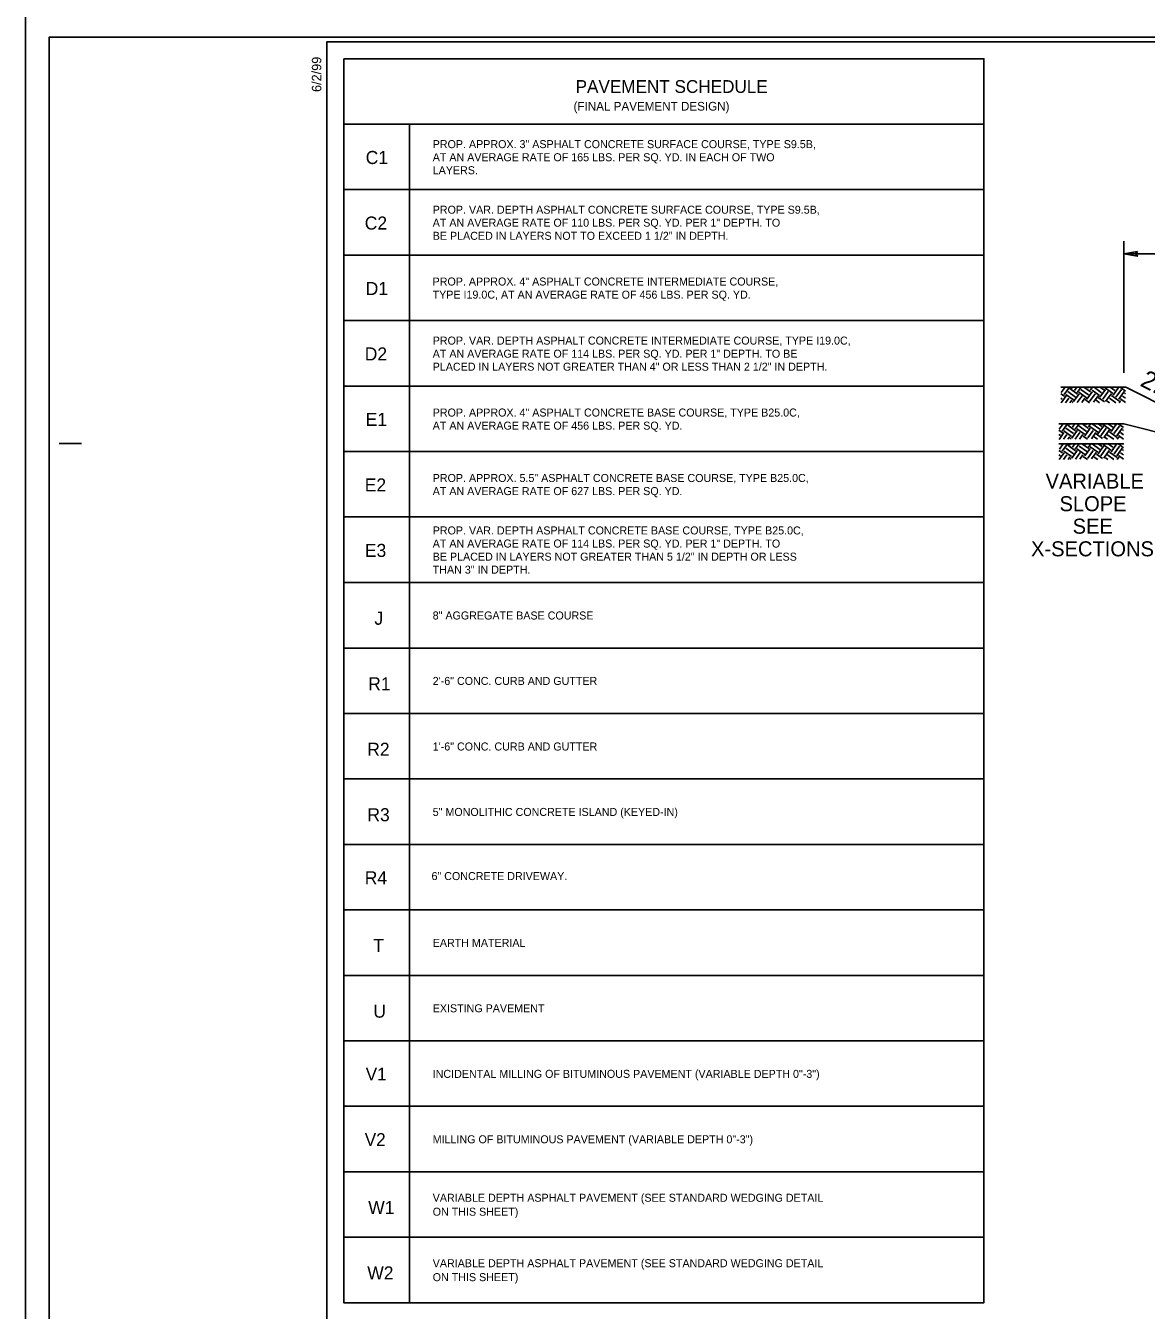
# Model space of a CAD drawing. Extents: x 3025871 to 3026431, y 707165 to 707825.
# Drawn here: x 3026022 to 3026115.2, y 707626.1 to 707732.9 of the extents above; entities that cross this region are included whole.
import ezdxf

# ---------------------------------------------------------------- set-up
doc = ezdxf.new("R2010")
doc.units = 0
for name, color, linetype in [('Default', 7, 'Continuous'), ('Old_Level_39', 7, 'Continuous'), ('Prop Drainage Structure Plot Symbol 20 Scale', 7, 'Continuous'), ('Sheet Cutting Line CELL', 7, 'Continuous'), ('Typical Guardrail CELL', 7, 'Continuous'), ('Typical ID Circle CELL', 7, 'Continuous'), ('Typical Shoulder Slope CELL', 7, 'Continuous'), ('Typical Terminator CELL', 7, 'Continuous'), ('Typical Text Centerline CELL', 7, 'Continuous'), ('Typical Text Grade Point CELL', 7, 'Continuous')]:
    doc.layers.add(name, color=color, linetype=linetype)

msp = doc.modelspace()

# ---------------------------------------------------------------- linework, layer by layer
at = {"layer": 'Default'}
msp.add_line((3026048.47, 707627.53), (3026048.47, 707627.53), dxfattribs=at)
msp.add_lwpolyline([(3026048.47, 707730.18), (3026101.69, 707730.18), (3026101.69, 707724.74), (3026048.47, 707724.74)], close=True, dxfattribs=at)
at = {"layer": 'Old_Level_39'}
msp.add_lwpolyline([(3026273.95, 707731.97), (3026023.97, 707731.97), (3026023.97, 707573.7), (3026273.95, 707573.7)], close=True, dxfattribs=at)
at = {"layer": 'Sheet Cutting Line CELL'}
msp.add_line((3026024.8, 707698.21), (3026026.67, 707698.21), dxfattribs=at)
msp.add_lwpolyline([(3026272.07, 707731.59), (3026047.07, 707731.59), (3026047.07, 707574.09), (3026272.07, 707574.09)], close=True, dxfattribs=at)
at = {"layer": 'Typical Guardrail CELL'}
for p, q in [((3026111.65, 707702.72), (3026111.66, 707702.7)), ((3026113.47, 707702.88), (3026125.81, 707696.71)), ((3026111.66, 707699.7), (3026111.67, 707699.68)), ((3026113.31, 707699.84), (3026125.81, 707696.71)), ((3026111.66, 707698.03), (3026111.67, 707698.01))]:
    msp.add_line(p, q, dxfattribs=at)
at = {"layer": 'Typical ID Circle CELL'}
for points in [[(3026053.92, 707719.3), (3026048.47, 707719.3), (3026048.47, 707724.74), (3026101.69, 707724.74), (3026101.69, 707719.3), (3026053.92, 707719.3), (3026053.92, 707724.74)], [(3026053.92, 707713.86), (3026048.47, 707713.86), (3026048.47, 707719.3), (3026101.69, 707719.3), (3026101.69, 707713.86), (3026053.92, 707713.86), (3026053.92, 707719.3)], [(3026053.92, 707708.41), (3026048.47, 707708.41), (3026048.47, 707713.86), (3026101.69, 707713.86), (3026101.69, 707708.41), (3026053.92, 707708.41), (3026053.92, 707713.86)], [(3026053.92, 707702.97), (3026048.47, 707702.97), (3026048.47, 707708.41), (3026101.69, 707708.41), (3026101.69, 707702.97), (3026053.92, 707702.97), (3026053.92, 707708.41)], [(3026053.92, 707697.53), (3026048.47, 707697.53), (3026048.47, 707702.97), (3026101.69, 707702.97), (3026101.69, 707697.53), (3026053.92, 707697.53), (3026053.92, 707702.97)], [(3026053.92, 707692.09), (3026048.47, 707692.09), (3026048.47, 707697.53), (3026101.69, 707697.53), (3026101.69, 707692.09), (3026053.92, 707692.09), (3026053.92, 707697.53)], [(3026053.92, 707686.65), (3026048.47, 707686.65), (3026048.47, 707692.09), (3026101.69, 707692.09), (3026101.69, 707686.65), (3026053.92, 707686.65), (3026053.92, 707692.09)], [(3026053.92, 707681.2), (3026048.47, 707681.2), (3026048.47, 707686.65), (3026101.69, 707686.65), (3026101.69, 707681.2), (3026053.92, 707681.2), (3026053.92, 707686.65)], [(3026053.92, 707675.76), (3026048.47, 707675.76), (3026048.47, 707681.2), (3026101.69, 707681.2), (3026101.69, 707675.76), (3026053.92, 707675.76), (3026053.92, 707681.2)], [(3026053.92, 707670.32), (3026048.47, 707670.32), (3026048.47, 707675.76), (3026101.69, 707675.76), (3026101.69, 707670.32), (3026053.92, 707670.32), (3026053.92, 707675.76)], [(3026053.92, 707664.88), (3026048.47, 707664.88), (3026048.47, 707670.32), (3026101.69, 707670.32), (3026101.69, 707664.88), (3026053.92, 707664.88), (3026053.92, 707670.32)], [(3026053.92, 707659.43), (3026048.47, 707659.43), (3026048.47, 707664.88), (3026101.69, 707664.88), (3026101.69, 707659.43), (3026053.92, 707659.43), (3026053.92, 707664.88)], [(3026053.92, 707653.99), (3026048.47, 707653.99), (3026048.47, 707659.44), (3026101.69, 707659.44), (3026101.69, 707653.99), (3026053.92, 707653.99), (3026053.92, 707659.44)], [(3026053.92, 707648.55), (3026048.47, 707648.55), (3026048.47, 707653.99), (3026101.69, 707653.99), (3026101.69, 707648.55), (3026053.92, 707648.55), (3026053.92, 707653.99)], [(3026053.92, 707643.11), (3026048.47, 707643.11), (3026048.47, 707648.55), (3026101.69, 707648.55), (3026101.69, 707643.11), (3026053.92, 707643.11), (3026053.92, 707648.55)], [(3026053.92, 707637.67), (3026048.47, 707637.67), (3026048.47, 707643.11), (3026101.69, 707643.11), (3026101.69, 707637.67), (3026053.92, 707637.67), (3026053.92, 707643.11)], [(3026053.92, 707632.22), (3026048.47, 707632.22), (3026048.47, 707637.67), (3026101.69, 707637.67), (3026101.69, 707632.22), (3026053.92, 707632.22), (3026053.92, 707637.67)], [(3026053.92, 707626.78), (3026048.47, 707626.78), (3026048.47, 707632.22), (3026101.69, 707632.22), (3026101.69, 707626.78), (3026053.92, 707626.78), (3026053.92, 707632.22)]]:
    msp.add_lwpolyline(points, dxfattribs=at)
at = {"layer": 'Typical Shoulder Slope CELL'}
for p, q in [((3026113.31, 707704.08), (3026113.31, 707715.03)), ((3026125.81, 707713.96), (3026113.31, 707713.96))]:
    msp.add_line(p, q, dxfattribs=at)
at = {"layer": 'Typical Terminator CELL'}
msp.add_lwpolyline([(3026274.62, 707735.34), (3026022.02, 707735.34), (3026022.02, 707570.34), (3026274.62, 707570.34)], close=True, dxfattribs=at)
at = {"layer": 'Typical Text Centerline CELL'}
msp.add_lwpolyline([(3026114.44, 707714.15), (3026113.31, 707713.96), (3026114.44, 707713.76), (3026114.3, 707713.96)], close=True, dxfattribs=at)
at = {"layer": 'Typical Text Grade Point CELL'}
for p, q in [((3026113.47, 707702.88), (3026108.07, 707702.88)), ((3026108.37, 707702.12), (3026108.07, 707702.34)), ((3026108.11, 707702.43), (3026108.43, 707702.88)), ((3026108.35, 707702.26), (3026108.79, 707702.88)), ((3026109.29, 707702.06), (3026108.66, 707702.52)), ((3026109.46, 707702.3), (3026108.83, 707702.76)), ((3026108.96, 707702.78), (3026109.03, 707702.88)), ((3026109.14, 707701.69), (3026109.6, 707702.32)), ((3026109.2, 707702.61), (3026109.4, 707702.89)), ((3026109.44, 707702.44), (3026109.76, 707702.88)), ((3026110.21, 707702), (3026109.58, 707702.46)), ((3026110.38, 707702.24), (3026109.75, 707702.7)), ((3026110.55, 707702.48), (3026109.99, 707702.89)), ((3026110.23, 707701.87), (3026110.69, 707702.5)), ((3026110.29, 707702.79), (3026110.36, 707702.89)), ((3026110.47, 707701.7), (3026110.93, 707702.33)), ((3026110.53, 707702.62), (3026110.72, 707702.88)), ((3026111.3, 707702.18), (3026110.67, 707702.64)), ((3026111.47, 707702.42), (3026110.84, 707702.88)), ((3026111.32, 707702.05), (3026111.78, 707702.68)), ((3026111.64, 707702.66), (3026111.33, 707702.88)), ((3026111.56, 707701.88), (3026112.02, 707702.51)), ((3026111.62, 707702.8), (3026111.68, 707702.88)), ((3026112.39, 707702.36), (3026111.76, 707702.82)), ((3026111.8, 707701.7), (3026112.26, 707702.34)), ((3026112.56, 707702.6), (3026112.17, 707702.88)), ((3026112.42, 707702.23), (3026112.87, 707702.86)), ((3026112.65, 707702.05), (3026113.11, 707702.69)), ((3026112.73, 707702.84), (3026112.68, 707702.88)), ((3026112.89, 707701.88), (3026113.35, 707702.52)), ((3026113.45, 707702.56), (3026113.01, 707702.88)), ((3026113.45, 707702.32), (3026113.37, 707702.38)), ((3026108.2, 707701.89), (3026108.07, 707701.98)), ((3026108.1, 707701.58), (3026108.51, 707702.15)), ((3026108.47, 707701.58), (3026108.75, 707701.97)), ((3026109.12, 707701.83), (3026108.49, 707702.28)), ((3026108.83, 707701.59), (3026108.98, 707701.8)), ((3026109.1, 707701.6), (3026109.01, 707701.67)), ((3026109.44, 707701.6), (3026109.84, 707702.15)), ((3026109.81, 707701.61), (3026110.08, 707701.98)), ((3026110.46, 707701.59), (3026110.1, 707701.85)), ((3026110.79, 707701.63), (3026111.17, 707702.16)), ((3026111.3, 707701.59), (3026111.02, 707701.79)), ((3026111.71, 707701.65), (3026111.19, 707702.02)), ((3026112.13, 707701.59), (3026111.94, 707701.73)), ((3026112.64, 707701.59), (3026112.11, 707701.96)), ((3026112.91, 707701.75), (3026112.28, 707702.2)), ((3026112.92, 707701.59), (3026113.05, 707701.77)), ((3026113.45, 707701.6), (3026113.03, 707701.91)), ((3026113.45, 707701.96), (3026113.2, 707702.14)), ((3026113.31, 707699.84), (3026107.91, 707699.84)), ((3026108.21, 707699.08), (3026107.91, 707699.3)), ((3026107.94, 707698.54), (3026108.34, 707699.11)), ((3026107.95, 707699.39), (3026108.27, 707699.84)), ((3026108.19, 707699.22), (3026108.63, 707699.84)), ((3026108.96, 707698.79), (3026108.32, 707699.24)), ((3026109.13, 707699.03), (3026108.49, 707699.48)), ((3026109.3, 707699.26), (3026108.66, 707699.72)), ((3026108.8, 707699.74), (3026108.87, 707699.84)), ((3026108.98, 707698.65), (3026109.44, 707699.29)), ((3026109.04, 707699.57), (3026109.24, 707699.85)), ((3026109.28, 707699.4), (3026109.59, 707699.84)), ((3026109.28, 707698.57), (3026109.67, 707699.11)), ((3026110.05, 707698.97), (3026109.41, 707699.42)), ((3026110.22, 707699.2), (3026109.58, 707699.66)), ((3026110.39, 707699.44), (3026109.82, 707699.85)), ((3026110.07, 707698.83), (3026110.53, 707699.46)), ((3026110.13, 707699.75), (3026110.2, 707699.85)), ((3026110.31, 707698.66), (3026110.76, 707699.29)), ((3026110.37, 707699.58), (3026110.56, 707699.85)), ((3026111.14, 707699.14), (3026110.5, 707699.6)), ((3026110.62, 707698.59), (3026111, 707699.12)), ((3026111.31, 707699.38), (3026110.67, 707699.84)), ((3026111.16, 707699.01), (3026111.62, 707699.64)), ((3026111.48, 707699.62), (3026111.17, 707699.84)), ((3026111.4, 707698.84), (3026111.85, 707699.47)), ((3026111.46, 707699.76), (3026111.52, 707699.84)), ((3026112.23, 707699.32), (3026111.59, 707699.78)), ((3026111.64, 707698.67), (3026112.09, 707699.3)), ((3026112.4, 707699.56), (3026112.01, 707699.84)), ((3026112.75, 707698.71), (3026112.11, 707699.16)), ((3026112.25, 707699.19), (3026112.71, 707699.82)), ((3026112.49, 707699.02), (3026112.95, 707699.65)), ((3026112.57, 707699.8), (3026112.51, 707699.84)), ((3026112.73, 707698.84), (3026113.18, 707699.48)), ((3026113.29, 707699.53), (3026112.85, 707699.84)), ((3026113.29, 707698.92), (3026113.03, 707699.1)), ((3026113.29, 707699.28), (3026113.21, 707699.34)), ((3026108.04, 707698.85), (3026107.91, 707698.94)), ((3026113.31, 707698.16), (3026107.92, 707698.16)), ((3026107.96, 707697.72), (3026108.28, 707698.16)), ((3026108.19, 707697.55), (3026108.64, 707698.16)), ((3026108.3, 707698.55), (3026108.58, 707698.94)), ((3026108.67, 707698.55), (3026108.82, 707698.76)), ((3026109.31, 707697.59), (3026108.67, 707698.05)), ((3026108.81, 707698.07), (3026108.88, 707698.16)), ((3026108.94, 707698.56), (3026108.84, 707698.63)), ((3026109.05, 707697.9), (3026109.25, 707698.18)), ((3026109.28, 707697.73), (3026109.6, 707698.16)), ((3026109.64, 707698.57), (3026109.91, 707698.94)), ((3026110.4, 707697.77), (3026109.83, 707698.17)), ((3026110.3, 707698.55), (3026109.93, 707698.81)), ((3026110.14, 707698.08), (3026110.21, 707698.17)), ((3026110.37, 707697.9), (3026110.57, 707698.17)), ((3026111.32, 707697.71), (3026110.68, 707698.16)), ((3026111.13, 707698.55), (3026110.85, 707698.75)), ((3026111.55, 707698.61), (3026111.02, 707698.99)), ((3026111.49, 707697.95), (3026111.18, 707698.17)), ((3026111.47, 707698.08), (3026111.53, 707698.17)), ((3026112.24, 707697.65), (3026111.6, 707698.11)), ((3026111.97, 707698.55), (3026111.77, 707698.69)), ((3026112.47, 707698.55), (3026111.94, 707698.93)), ((3026112.41, 707697.89), (3026112.02, 707698.17)), ((3026112.26, 707697.51), (3026112.71, 707698.15)), ((3026112.58, 707698.13), (3026112.52, 707698.17)), ((3026112.75, 707698.55), (3026112.89, 707698.73)), ((3026113.29, 707698.56), (3026112.86, 707698.87)), ((3026113.29, 707697.85), (3026112.86, 707698.17)), ((3026108.22, 707697.41), (3026107.92, 707697.63)), ((3026108.04, 707697.17), (3026107.92, 707697.26)), ((3026107.94, 707696.87), (3026108.35, 707697.43)), ((3026108.31, 707696.87), (3026108.59, 707697.26)), ((3026108.96, 707697.11), (3026108.33, 707697.57)), ((3026109.14, 707697.35), (3026108.5, 707697.81)), ((3026108.68, 707696.88), (3026108.83, 707697.09)), ((3026108.95, 707696.89), (3026108.85, 707696.95)), ((3026108.99, 707696.98), (3026109.44, 707697.61)), ((3026109.29, 707696.89), (3026109.68, 707697.44)), ((3026110.06, 707697.29), (3026109.42, 707697.75)), ((3026110.23, 707697.53), (3026109.59, 707697.99)), ((3026109.65, 707696.9), (3026109.92, 707697.27)), ((3026110.3, 707696.87), (3026109.94, 707697.13)), ((3026110.08, 707697.16), (3026110.53, 707697.79)), ((3026110.32, 707696.98), (3026110.77, 707697.62)), ((3026111.15, 707697.47), (3026110.51, 707697.93)), ((3026110.63, 707696.92), (3026111.01, 707697.45)), ((3026111.14, 707696.87), (3026110.86, 707697.07)), ((3026111.55, 707696.94), (3026111.03, 707697.31)), ((3026111.17, 707697.33), (3026111.62, 707697.97)), ((3026111.41, 707697.16), (3026111.86, 707697.8)), ((3026111.64, 707696.99), (3026112.1, 707697.63)), ((3026111.98, 707696.87), (3026111.78, 707697.01)), ((3026112.48, 707696.87), (3026111.95, 707697.25)), ((3026112.76, 707697.03), (3026112.12, 707697.49)), ((3026112.5, 707697.34), (3026112.95, 707697.98)), ((3026112.73, 707697.17), (3026113.19, 707697.81)), ((3026112.76, 707696.87), (3026112.89, 707697.06)), ((3026113.29, 707696.89), (3026112.87, 707697.19)), ((3026113.29, 707697.25), (3026113.04, 707697.43)), ((3026113.29, 707697.61), (3026113.21, 707697.67))]:
    msp.add_line(p, q, dxfattribs=at)

# ---------------------------------------------------------------- texts
at = {"layer": 'Default'}
for s, height, p in [('PAVEMENT SCHEDULE', 1.0642, (3026067.74, 707727.34)), ('(FINAL PAVEMENT DESIGN)', 0.7239, (3026067.57, 707725.87))]:
    msp.add_text(s, height=height, dxfattribs=at).set_placement(p)
at = {"layer": 'Prop Drainage Structure Plot Symbol 20 Scale'}
for s, p in [('VARIABLE', (3026106.81, 707694.45)), ('SLOPE', (3026107.97, 707692.57)), ('SEE', (3026109.06, 707690.7)), ('X-SECTIONS', (3026105.6, 707688.82))]:
    msp.add_text(s, height=1.25, dxfattribs=at).set_placement(p)
at = {"layer": 'Sheet Cutting Line CELL'}
msp.add_text('6/2/99', height=0.787, rotation=90, dxfattribs=at).set_placement((3026046.6, 707727.42))
at = {"layer": 'Typical Guardrail CELL'}
msp.add_text('2:1 MAX.', height=1.5, rotation=333.435, dxfattribs=at).set_placement((3026114.59, 707703.03))
at = {"layer": 'Typical ID Circle CELL'}
for s, height, p in [('PROP. APPROX. 3" ASPHALT CONCRETE SURFACE COURSE, TYPE S9.5B, ', 0.6652, (3026055.86, 707722.75)), ('C1', 1.086, (3026050.29, 707721.43)), ('AT AN AVERAGE RATE OF 165 LBS. PER SQ. YD. IN EACH OF TWO ', 0.6652, (3026055.86, 707721.66)), ('LAYERS.', 0.665, (3026055.86, 707720.58)), ('PROP. VAR. DEPTH ASPHALT CONCRETE SURFACE COURSE, TYPE S9.5B,', 0.6652, (3026055.86, 707717.3)), ('C2', 1.086, (3026050.21, 707715.98)), ('AT AN AVERAGE RATE OF 110 LBS. PER SQ. YD. PER 1" DEPTH. TO', 0.6652, (3026055.86, 707716.22)), ('BE PLACED IN LAYERS NOT TO EXCEED 1 1/2" IN DEPTH.', 0.6652, (3026055.86, 707715.13)), ('PROP. APPROX. 4" ASPHALT CONCRETE INTERMEDIATE COURSE,', 0.6652, (3026055.85, 707711.33)), ('D1', 1.086, (3026050.29, 707710.54)), ('TYPE I19.0C, AT AN AVERAGE RATE OF 456 LBS. PER SQ. YD.', 0.6652, (3026055.85, 707710.24)), ('PROP. VAR. DEPTH ASPHALT CONCRETE INTERMEDIATE COURSE, TYPE I19.0C,', 0.6652, (3026055.86, 707706.42)), ('D2', 1.086, (3026050.21, 707705.1)), ('AT AN AVERAGE RATE OF 114 LBS. PER SQ. YD. PER 1" DEPTH. TO BE', 0.6652, (3026055.86, 707705.33)), ('PLACED IN LAYERS NOT GREATER THAN 4" OR LESS THAN 2 1/2" IN DEPTH.', 0.6652, (3026055.86, 707704.25)), ('E1', 1.086, (3026050.29, 707699.66)), ('PROP. APPROX. 4" ASPHALT CONCRETE BASE COURSE, TYPE B25.0C,', 0.6652, (3026055.86, 707700.44)), ('AT AN AVERAGE RATE OF 456 LBS. PER SQ. YD.', 0.6652, (3026055.86, 707699.35)), ('E2', 1.086, (3026050.21, 707694.21)), ('PROP. APPROX. 5.5" ASPHALT CONCRETE BASE COURSE, TYPE B25.0C,', 0.6652, (3026055.86, 707695)), ('AT AN AVERAGE RATE OF 627 LBS. PER SQ. YD.', 0.6652, (3026055.86, 707693.91)), ('PROP. VAR. DEPTH ASPHALT CONCRETE BASE COURSE, TYPE B25.0C,', 0.6652, (3026055.86, 707690.64)), ('E3', 1.086, (3026050.22, 707688.77)), ('AT AN AVERAGE RATE OF 114 LBS. PER SQ. YD. PER 1" DEPTH. TO', 0.6652, (3026055.86, 707689.55)), ('BE PLACED IN LAYERS NOT GREATER THAN 5 1/2" IN DEPTH OR LESS', 0.6652, (3026055.86, 707688.46)), ('THAN 3" IN DEPTH.', 0.6652, (3026055.86, 707687.38)), ('J', 1.09, (3026051.01, 707683.13)), ('8" AGGREGATE BASE COURSE', 0.6652, (3026055.86, 707683.57)), ('2\'-6" CONC. CURB AND GUTTER', 0.6652, (3026055.86, 707678.13)), ('R1', 1.086, (3026050.5, 707677.68)), ('R2', 1.086, (3026050.42, 707672.24)), ('1\'-6" CONC. CURB AND GUTTER', 0.6652, (3026055.86, 707672.68)), ('R3', 1.086, (3026050.43, 707666.8)), ('5" MONOLITHIC CONCRETE ISLAND (KEYED-IN)', 0.6652, (3026055.86, 707667.24)), ('R4', 1.086, (3026050.21, 707661.56)), ('6" CONCRETE DRIVEWAY.', 0.6652, (3026055.76, 707661.91)), ('T', 1.09, (3026050.92, 707655.92)), ('EARTH MATERIAL', 0.6652, (3026055.86, 707656.36)), ('U', 1.09, (3026050.92, 707650.47)), ('EXISTING PAVEMENT', 0.6652, (3026055.86, 707650.92)), ('V1', 1.064, (3026050.29, 707645.25)), ('INCIDENTAL MILLING OF BITUMINOUS PAVEMENT (VARIABLE DEPTH 0"-3")', 0.6652, (3026055.86, 707645.47)), ('V2', 1.064, (3026050.21, 707639.81)), ('MILLING OF BITUMINOUS PAVEMENT (VARIABLE DEPTH 0"-3")', 0.6652, (3026055.86, 707640.03)), ('W1', 1.086, (3026050.5, 707634.15)), ('VARIABLE DEPTH ASPHALT PAVEMENT (SEE STANDARD WEDGING DETAIL', 0.6652, (3026055.86, 707635.17)), ('ON THIS SHEET)', 0.6652, (3026055.86, 707634.01)), ('W2', 1.086, (3026050.42, 707628.71)), ('VARIABLE DEPTH ASPHALT PAVEMENT (SEE STANDARD WEDGING DETAIL', 0.6652, (3026055.86, 707629.73)), ('ON THIS SHEET)', 0.6652, (3026055.86, 707628.57))]:
    msp.add_text(s, height=height, dxfattribs=at).set_placement(p)

doc.saveas('drawing.dxf')
